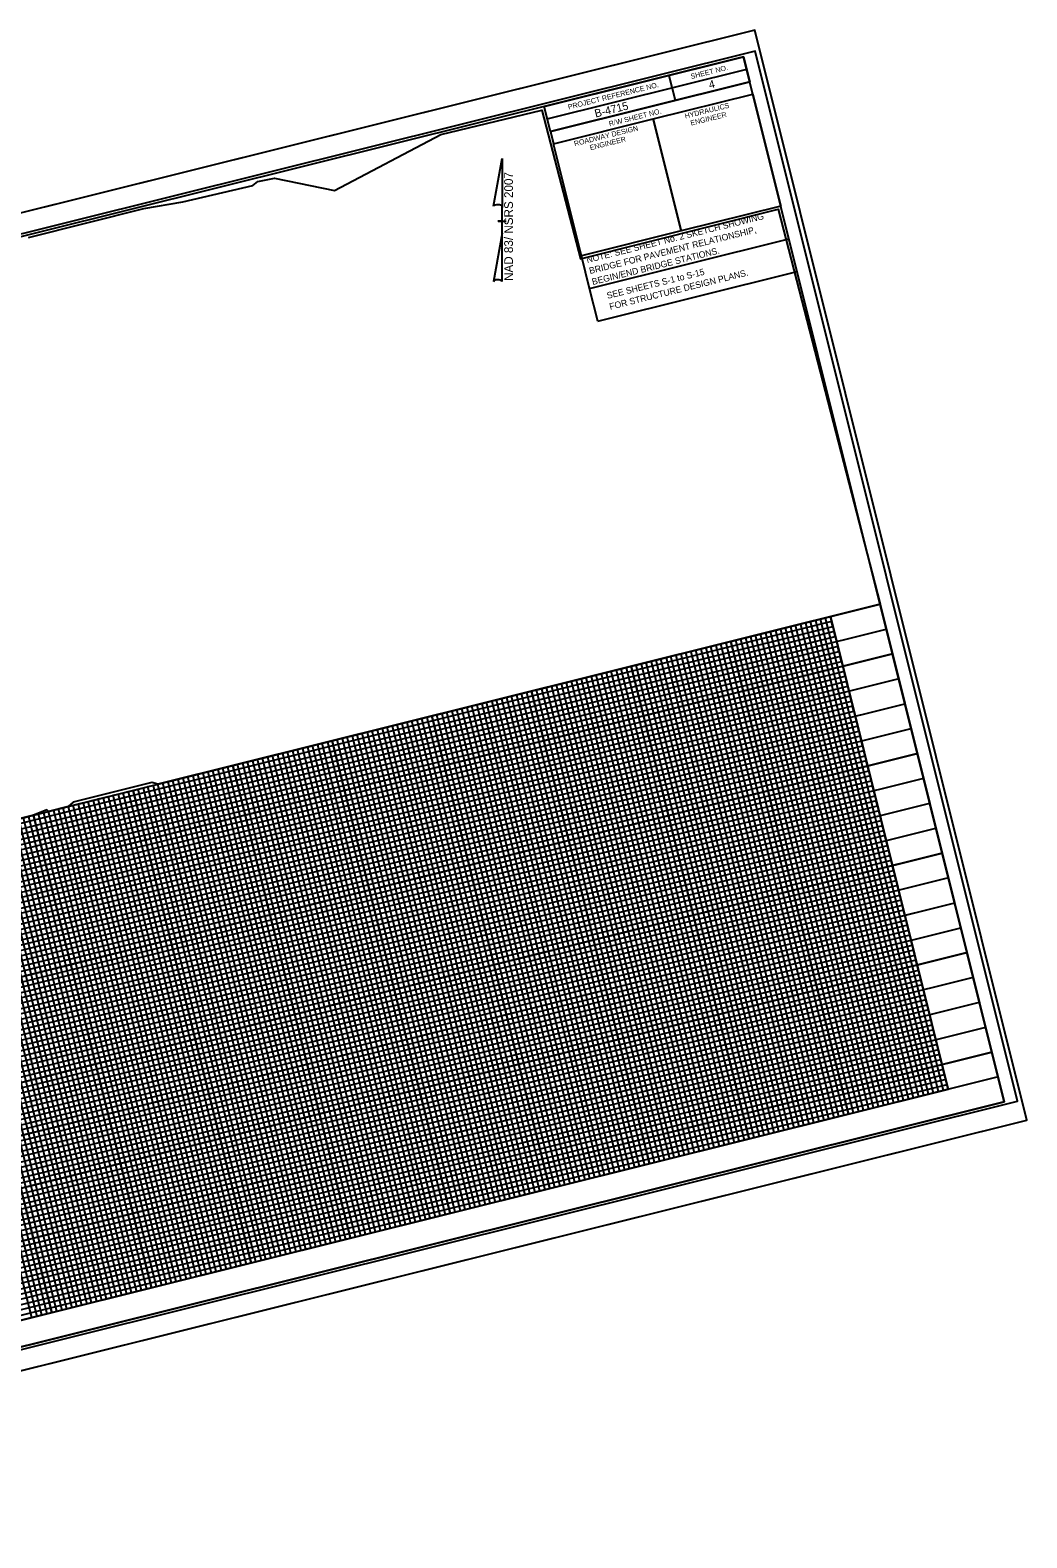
# Model space of a CAD drawing. Extents: x 1030486 to 1032384, y 655714 to 657184.
# Drawn here: x 1031413 to 1032384, y 655714 to 657184 of the extents above; entities that cross this region are included whole.
import ezdxf

# ---------------------------------------------------------------- set-up
doc = ezdxf.new("R2010")
doc.units = 0
for name, color, linetype in [('Prop Horizontal Alignment Station Label', 7, 'Continuous'), ('Prop North Arrow NAD83 for Plan Sheets CELL', 7, 'Continuous'), ('Prop Paved Shoulder', 7, 'Continuous'), ('Sheet Clip Boundary CELL', 7, 'Continuous'), ('Sheet Cutting Line CELL', 7, 'Continuous'), ('Sheet Data Field CELL', 7, 'Continuous'), ('Sheet DOT Grid CELL', 7, 'Continuous'), ('Sheet Layout Plan Border', 7, 'Continuous'), ('Sheet Layout Profile Border Port 2', 7, 'Continuous'), ('Sheet Plan And Profile CELL', 7, 'Continuous'), ('Sheet Plot Border Inside CELL', 7, 'Continuous'), ('Sheet Plot Border Outside CELL', 7, 'Continuous'), ('Sheet Profile Grid Major CELL', 7, 'Continuous'), ('Sheet Profile Grid Middle CELL', 7, 'Continuous'), ('Sheet Profile Grid Minor CELL', 7, 'Continuous')]:
    doc.layers.add(name, color=color, linetype=linetype)

msp = doc.modelspace()

# ---------------------------------------------------------------- linework, layer by layer
at = {"layer": 'Prop North Arrow NAD83 for Plan Sheets CELL'}
for p, q in [((1031864.6, 657012.3), (1031872.8, 657058.7)), ((1031872.9, 657058.7), (1031872.8, 657058.7)), ((1031872.9, 657058.7), (1031872.8, 657058.7)), ((1031872.9, 657058.7), (1031872.9, 657010.9)), ((1031872.9, 656986.1), (1031872.9, 657012.3)), ((1031872.9, 657010.9), (1031872.9, 657012.2)), ((1031868.9, 656997.7), (1031868.8, 656997.7)), ((1031868.9, 656997.7), (1031876.9, 656997.7)), ((1031872.4, 656997.7), (1031868.9, 656997.7)), ((1031872.9, 656986.1), (1031864.5, 656938.8)), ((1031872.9, 656939), (1031872.9, 656986.1))]:
    msp.add_line(p, q, dxfattribs=at)
for centre, start_param, end_param in [((1031868.7, 657011.8), 0.216388, 2.908219), ((1031868.7, 656938.6), 0.201328, 3.141593)]:
    msp.add_ellipse(centre, major_axis=(4.23, -0.03), ratio=0.461098, start_param=start_param, end_param=end_param, dxfattribs=at)
at = {"layer": 'Prop Paved Shoulder'}
msp.add_arc((1031481.8, 656722.1), 40, 14, 14, dxfattribs=at)
at = {"layer": 'Sheet Clip Boundary CELL'}
msp.add_lwpolyline([(1031411.6, 656981.9), (1031524, 657010.1), (1031562, 657016.5), (1031630.1, 657032.5), (1031634.9, 657036.5), (1031651.2, 657039.7), (1031709.5, 657027.5), (1031813, 657082.1), (1031911.7, 657106), (1031949.3, 656960.9), (1032141.6, 657009.3), (1032241.1, 656624.3), (1031853, 656527.5), (1031537.6, 656448.9), (1031531.8, 656450.5), (1031455, 656431.2), (1031450.3, 656427.1), (1031430.9, 656422.3), (1031429.3, 656423.7), (1031416.3, 656418.7), (1031314.4, 656393.3)], dxfattribs=at)
at = {"layer": 'Sheet Cutting Line CELL'}
for p, q in [((1032119.1, 657183.9), (1030485.6, 656776.6)), ((1030750.5, 655714.1), (1032384, 656121.4))]:
    msp.add_line(p, q, dxfattribs=at)
at = {"layer": 'Sheet DOT Grid CELL'}
for p, q in [((1030785.6, 656261.4), (1032241.1, 656624.3)), ((1032192.6, 656612.2), (1032307.5, 656151.3)), ((1032144, 656600.1), (1032259, 656139.2)), ((1032095.5, 656588), (1032210.4, 656127.1)), ((1030797.7, 656212.9), (1032253.2, 656575.8)), ((1032047, 656575.9), (1032161.9, 656115)), ((1031998.5, 656563.8), (1032113.4, 656102.9)), ((1031901.5, 656539.6), (1032016.4, 656078.7)), ((1031950, 656551.7), (1032064.9, 656090.8)), ((1030809.8, 656164.4), (1032265.3, 656527.3)), ((1031853, 656527.5), (1031967.9, 656066.6)), ((1031804.4, 656515.4), (1031919.4, 656054.5)), ((1031755.9, 656503.3), (1031870.8, 656042.4)), ((1030821.9, 656115.9), (1032277.4, 656478.7)), ((1031658.9, 656479.1), (1031773.8, 656018.2)), ((1031707.4, 656491.2), (1031822.3, 656030.3)), ((1031610.4, 656467), (1031725.3, 656006.1)), ((1031561.9, 656454.9), (1031676.8, 655994.1)), ((1031513.4, 656442.8), (1031628.3, 655982)), ((1030834, 656067.3), (1032289.5, 656430.2)), ((1031464.8, 656430.8), (1031579.8, 655969.9)), ((1031367.8, 656406.6), (1031482.7, 655945.7)), ((1031416.3, 656418.7), (1031531.2, 655957.8)), ((1031319.3, 656394.5), (1031434.2, 655933.6)), ((1030846.1, 656018.8), (1032301.6, 656381.7)), ((1030858.2, 655970.3), (1032313.7, 656333.2)), ((1030870.3, 655921.8), (1032325.7, 656284.7)), ((1030882.4, 655873.3), (1032337.8, 656236.2)), ((1030894.5, 655824.8), (1032349.9, 656187.7))]:
    msp.add_line(p, q, dxfattribs=at)
at = {"layer": 'Sheet Layout Plan Border'}
msp.add_lwpolyline([(1030906.6, 655776.3), (1030785.6, 656261.4), (1031949.9, 656551.7), (1032241.1, 656624.3), (1032362, 656139.1)], close=True, dxfattribs=at)
at = {"layer": 'Sheet Layout Profile Border Port 2'}
msp.add_lwpolyline([(1030834.1, 656273.5), (1032192.6, 656612.2), (1032307.5, 656151.3), (1030949.1, 655812.6)], close=True, dxfattribs=at)
at = {"layer": 'Sheet Plan And Profile CELL'}
for p, q in [((1031916.9, 657097.4), (1032111.1, 657145.8)), ((1032035.3, 657139.8), (1032041.3, 657115.5)), ((1031920, 657085.2), (1032114.1, 657133.6)), ((1032020.1, 657097.3), (1032047.3, 656988.2)), ((1031920, 657085.2), (1031923, 657073.1)), ((1031958.1, 656932.1), (1032152.3, 656980.5)), ((1031958.1, 656932.1), (1031950.2, 656964)), ((1031966.1, 656900.3), (1032160.2, 656948.7)), ((1031966.1, 656900.3), (1031958.1, 656932.1)), ((1032356, 656163.4), (1030900.5, 655800.5))]:
    msp.add_line(p, q, dxfattribs=at)
for points in [[(1032108, 657158), (1030652.6, 656795.1), (1030906.6, 655776.3), (1032362, 656139.1)], [(1031913.9, 657109.6), (1032108, 657158), (1032114.1, 657133.6), (1031920, 657085.2)], [(1032020.1, 657097.3), (1032117.1, 657121.5), (1032144.3, 657012.4), (1032047.3, 656988.2)], [(1031923, 657073.1), (1032020.1, 657097.3), (1032047.3, 656988.2), (1031950.2, 656964)]]:
    msp.add_lwpolyline(points, close=True, dxfattribs=at)
at = {"layer": 'Sheet Plot Border Inside CELL'}
msp.add_lwpolyline([(1030758.3, 655736.7), (1032374.8, 656139.7), (1032119.5, 657163.4), (1030503, 656760.4)], close=True, dxfattribs=at)
at = {"layer": 'Sheet Plot Border Outside CELL'}
msp.add_lwpolyline([(1030750.5, 655714.1), (1032384, 656121.4), (1032119.1, 657183.9), (1030485.6, 656776.6)], close=True, dxfattribs=at)
at = {"layer": 'Sheet Profile Grid Major CELL'}
for points in [[(1030785.6, 656261.4), (1032241.1, 656624.3)], [(1032307.5, 656151.3), (1032192.6, 656612.2)], [(1032210.4, 656127.1), (1032095.5, 656588), (1032144, 656600.1), (1032259, 656139.2)], [(1032253.2, 656575.8), (1030797.7, 656212.9), (1030809.8, 656164.4), (1032265.3, 656527.3)], [(1032113.4, 656102.9), (1031998.5, 656563.8), (1032047, 656575.9), (1032161.9, 656115)], [(1032016.4, 656078.7), (1031901.5, 656539.6), (1031950, 656551.7), (1032064.9, 656090.8)], [(1031919.4, 656054.5), (1031804.4, 656515.4), (1031853, 656527.5), (1031967.9, 656066.6)], [(1031822.3, 656030.3), (1031707.4, 656491.2), (1031755.9, 656503.3), (1031870.8, 656042.4)], [(1032277.4, 656478.7), (1030821.9, 656115.9), (1030834, 656067.3), (1032289.5, 656430.2)], [(1031725.3, 656006.1), (1031610.4, 656467), (1031658.9, 656479.1), (1031773.8, 656018.2)], [(1031628.3, 655982), (1031513.4, 656442.8), (1031561.9, 656454.9), (1031676.8, 655994.1)], [(1031531.2, 655957.8), (1031416.3, 656418.7), (1031464.8, 656430.8), (1031579.8, 655969.9)], [(1031434.2, 655933.6), (1031319.3, 656394.5), (1031367.8, 656406.6), (1031482.7, 655945.7)], [(1032301.6, 656381.7), (1030846.1, 656018.8), (1030858.2, 655970.3), (1032313.7, 656333.2)], [(1032325.7, 656284.7), (1030870.3, 655921.8), (1030882.4, 655873.3), (1032337.8, 656236.2)], [(1032349.9, 656187.7), (1030894.5, 655824.8)]]:
    msp.add_lwpolyline(points, dxfattribs=at)
at = {"layer": 'Sheet Profile Grid Middle CELL'}
for p, q in [((1030791.7, 656237.1), (1032247.1, 656600)), ((1032259.2, 656551.5), (1030803.8, 656188.6)), ((1030815.9, 656140.1), (1032271.3, 656503)), ((1032283.4, 656454.5), (1030828, 656091.6)), ((1030840.1, 656043.1), (1032295.5, 656406)), ((1032307.6, 656357.5), (1030852.2, 655994.6)), ((1030864.3, 655946.1), (1032319.7, 656308.9)), ((1032331.8, 656260.4), (1030876.4, 655897.5)), ((1030888.4, 655849), (1032343.9, 656211.9))]:
    msp.add_line(p, q, dxfattribs=at)
for points in [[(1032234.7, 656133.2), (1032119.8, 656594), (1032168.3, 656606.1), (1032283.2, 656145.3)], [(1032137.7, 656109), (1032022.8, 656569.9), (1032071.3, 656582), (1032186.2, 656121.1)], [(1032040.6, 656084.8), (1031925.7, 656545.7), (1031974.2, 656557.8), (1032089.2, 656096.9)], [(1031943.6, 656060.6), (1031828.7, 656521.5), (1031877.2, 656533.6), (1031992.1, 656072.7)], [(1031846.6, 656036.4), (1031731.7, 656497.3), (1031780.2, 656509.4), (1031895.1, 656048.5)], [(1031749.6, 656012.2), (1031634.6, 656473.1), (1031683.2, 656485.2), (1031798.1, 656024.3)], [(1031652.5, 655988), (1031537.6, 656448.9), (1031586.1, 656461), (1031701, 656000.1)], [(1031555.5, 655963.8), (1031440.6, 656424.7), (1031489.1, 656436.8), (1031604, 655975.9)], [(1031458.5, 655939.6), (1031343.6, 656400.5), (1031392.1, 656412.6), (1031507, 655951.7)]]:
    msp.add_lwpolyline(points, dxfattribs=at)
at = {"layer": 'Sheet Profile Grid Minor CELL'}
for points in [[(1032297.8, 656148.9), (1032182.9, 656609.8), (1032187.7, 656611), (1032302.6, 656150.1)], [(1030836.6, 656263.8), (1032195, 656602.5), (1032193.8, 656607.3), (1030835.4, 656268.7)], [(1030839, 656254.1), (1032197.4, 656592.8), (1032196.2, 656597.6), (1030837.8, 656258.9)], [(1032239.6, 656134.4), (1032124.6, 656595.3), (1032129.5, 656596.5), (1032244.4, 656135.6)], [(1032249.3, 656136.8), (1032134.3, 656597.7), (1032139.2, 656598.9), (1032254.1, 656138)], [(1032263.8, 656140.4), (1032148.9, 656601.3), (1032153.7, 656602.5), (1032268.7, 656141.6)], [(1032273.5, 656142.8), (1032158.6, 656603.7), (1032163.5, 656604.9), (1032278.4, 656144)], [(1032288.1, 656146.5), (1032173.2, 656607.4), (1032178, 656608.6), (1032292.9, 656147.7)], [(1030842.6, 656239.5), (1032201, 656578.2), (1032199.8, 656583.1), (1030841.4, 656244.4)], [(1032191, 656122.3), (1032076.1, 656583.2), (1032081, 656584.4), (1032195.9, 656123.5)], [(1032200.7, 656124.7), (1032085.8, 656585.6), (1032090.7, 656586.8), (1032205.6, 656125.9)], [(1032215.3, 656128.3), (1032100.4, 656589.2), (1032105.2, 656590.4), (1032220.1, 656129.5)], [(1032225, 656130.7), (1032110.1, 656591.6), (1032114.9, 656592.8), (1032229.8, 656131.9)], [(1030845, 656229.8), (1032203.4, 656568.5), (1032202.2, 656573.4), (1030843.8, 656234.7)], [(1032128, 656106.5), (1032013.1, 656567.4), (1032017.9, 656568.6), (1032132.8, 656107.8)], [(1032142.5, 656110.2), (1032027.6, 656571.1), (1032032.5, 656572.3), (1032147.4, 656111.4)], [(1032152.2, 656112.6), (1032037.3, 656573.5), (1032042.2, 656574.7), (1032157.1, 656113.8)], [(1032166.8, 656116.2), (1032051.9, 656577.1), (1032056.7, 656578.3), (1032171.6, 656117.4)], [(1032176.5, 656118.6), (1032061.6, 656579.5), (1032066.4, 656580.7), (1032181.3, 656119.9)], [(1030848.7, 656215.3), (1032207.1, 656554), (1032205.9, 656558.8), (1030847.5, 656220.1)], [(1032069.7, 656092), (1031954.8, 656552.9), (1031959.7, 656554.1), (1032074.6, 656093.2)], [(1032079.5, 656094.5), (1031964.5, 656555.3), (1031969.4, 656556.6), (1032084.3, 656095.7)], [(1032094, 656098.1), (1031979.1, 656559), (1031983.9, 656560.2), (1032098.9, 656099.3)], [(1032103.7, 656100.5), (1031988.8, 656561.4), (1031993.6, 656562.6), (1032108.6, 656101.7)], [(1032118.3, 656104.1), (1032003.4, 656565), (1032008.2, 656566.2), (1032123.1, 656105.3)], [(1030851.1, 656205.6), (1032209.5, 656544.3), (1032208.3, 656549.1), (1030849.9, 656210.4)], [(1032006.7, 656076.3), (1031891.8, 656537.2), (1031896.6, 656538.4), (1032011.5, 656077.5)], [(1032021.2, 656079.9), (1031906.3, 656540.8), (1031911.2, 656542), (1032026.1, 656081.1)], [(1032030.9, 656082.4), (1031916, 656543.2), (1031920.9, 656544.5), (1032035.8, 656083.6)], [(1032045.5, 656086), (1031930.6, 656546.9), (1031935.4, 656548.1), (1032050.3, 656087.2)], [(1032055.2, 656088.4), (1031940.3, 656549.3), (1031945.1, 656550.5), (1032060, 656089.6)], [(1030854.7, 656191), (1032213.1, 656529.7), (1032211.9, 656534.6), (1030853.5, 656195.9)], [(1030857.1, 656181.3), (1032215.5, 656520), (1032214.3, 656524.9), (1030855.9, 656186.2)], [(1031948.5, 656061.8), (1031833.5, 656522.7), (1031838.4, 656523.9), (1031953.3, 656063)], [(1031958.2, 656064.2), (1031843.3, 656525.1), (1031848.1, 656526.3), (1031963, 656065.4)], [(1031972.7, 656067.8), (1031857.8, 656528.7), (1031862.7, 656529.9), (1031977.6, 656069)], [(1031982.4, 656070.3), (1031867.5, 656531.1), (1031872.4, 656532.4), (1031987.3, 656071.5)], [(1031997, 656073.9), (1031882.1, 656534.8), (1031886.9, 656536), (1032001.8, 656075.1)], [(1030859.5, 656171.6), (1032218, 656510.3)], [(1031885.4, 656046.1), (1031770.5, 656507), (1031775.3, 656508.2), (1031890.2, 656047.3)], [(1031899.9, 656049.7), (1031785, 656510.6), (1031789.9, 656511.8), (1031904.8, 656050.9)], [(1031909.7, 656052.1), (1031794.7, 656513), (1031799.6, 656514.2), (1031914.5, 656053.3)], [(1031924.2, 656055.7), (1031809.3, 656516.6), (1031814.1, 656517.8), (1031929.1, 656057)], [(1031933.9, 656058.2), (1031819, 656519.1), (1031823.8, 656520.3), (1031938.8, 656059.4)], [(1030862, 656161.9), (1032220.4, 656500.6), (1032219.2, 656505.5), (1030860.8, 656166.8)], [(1030865.6, 656147.4), (1032224, 656486.1), (1032221.6, 656495.8), (1030863.2, 656157.1)], [(1031827.2, 656031.6), (1031712.3, 656492.4), (1031717.1, 656493.7), (1031832, 656032.8)], [(1031836.9, 656034), (1031722, 656494.9), (1031726.8, 656496.1), (1031841.7, 656035.2)], [(1031851.4, 656037.6), (1031736.5, 656498.5), (1031741.4, 656499.7), (1031856.3, 656038.8)], [(1031861.1, 656040), (1031746.2, 656500.9), (1031751.1, 656502.1), (1031866, 656041.2)], [(1031875.7, 656043.6), (1031760.8, 656504.5), (1031765.6, 656505.7), (1031880.5, 656044.9)], [(1030868, 656137.7), (1032226.4, 656476.4), (1032225.2, 656481.2), (1030866.8, 656142.5)], [(1031778.7, 656019.5), (1031663.7, 656480.3), (1031668.6, 656481.6), (1031783.5, 656020.7)], [(1031788.4, 656021.9), (1031673.5, 656482.8), (1031678.3, 656484), (1031793.2, 656023.1)], [(1031802.9, 656025.5), (1031688, 656486.4), (1031692.9, 656487.6), (1031807.8, 656026.7)], [(1031812.6, 656027.9), (1031697.7, 656488.8), (1031702.6, 656490), (1031817.5, 656029.1)], [(1030871.6, 656123.1), (1032230.1, 656461.8), (1032227.6, 656471.5), (1030869.2, 656132.8)], [(1031715.6, 656003.7), (1031600.7, 656464.6), (1031605.5, 656465.8), (1031720.4, 656004.9)], [(1031730.1, 656007.4), (1031615.2, 656468.2), (1031620.1, 656469.5), (1031735, 656008.6)], [(1031739.8, 656009.8), (1031624.9, 656470.7), (1031629.8, 656471.9), (1031744.7, 656011)], [(1031754.4, 656013.4), (1031639.5, 656474.3), (1031644.3, 656475.5), (1031759.3, 656014.6)], [(1031764.1, 656015.8), (1031649.2, 656476.7), (1031654, 656477.9), (1031769, 656017)], [(1030874.1, 656113.4), (1032232.5, 656452.1), (1032231.3, 656456.9), (1030872.9, 656118.3)], [(1031657.4, 655989.2), (1031542.5, 656450.1), (1031547.3, 656451.3), (1031662.2, 655990.4)], [(1031667.1, 655991.6), (1031552.2, 656452.5), (1031557, 656453.7), (1031671.9, 655992.8)], [(1031681.6, 655995.3), (1031566.7, 656456.2), (1031571.6, 656457.4), (1031686.5, 655996.5)], [(1031691.3, 655997.7), (1031576.4, 656458.6), (1031581.3, 656459.8), (1031696.2, 655998.9)], [(1031705.9, 656001.3), (1031591, 656462.2), (1031595.8, 656463.4), (1031710.7, 656002.5)], [(1030877.7, 656098.8), (1032236.1, 656437.5), (1032233.7, 656447.2), (1030875.3, 656108.6)], [(1031594.3, 655973.5), (1031479.4, 656434.4), (1031484.2, 656435.6), (1031599.2, 655974.7)], [(1031608.9, 655977.1), (1031493.9, 656438), (1031498.8, 656439.2), (1031613.7, 655978.3)], [(1031618.6, 655979.5), (1031503.6, 656440.4), (1031508.5, 656441.6), (1031623.4, 655980.7)], [(1031633.1, 655983.2), (1031518.2, 656444.1), (1031523.1, 656445.3), (1031638, 655984.4)], [(1031642.8, 655985.6), (1031527.9, 656446.5), (1031532.8, 656447.7), (1031647.7, 655986.8)], [(1030880.1, 656089.1), (1032238.5, 656427.8), (1032237.3, 656432.7), (1030878.9, 656094)], [(1030883.7, 656074.6), (1032242.2, 656413.3), (1032239.7, 656423), (1030881.3, 656084.3)], [(1031536.1, 655959), (1031421.2, 656419.9), (1031426, 656421.1), (1031540.9, 655960.2)], [(1031545.8, 655961.4), (1031430.9, 656422.3), (1031435.7, 656423.5), (1031550.6, 655962.6)], [(1031560.3, 655965), (1031445.4, 656425.9), (1031450.3, 656427.1), (1031565.2, 655966.2)], [(1031570, 655967.4), (1031455.1, 656428.3), (1031460, 656429.5), (1031574.9, 655968.7)], [(1031584.6, 655971.1), (1031469.7, 656432), (1031474.5, 656433.2), (1031589.5, 655972.3)], [(1030886.2, 656064.9), (1032244.6, 656403.6), (1032243.4, 656408.4), (1030884.9, 656069.7)], [(1031473, 655943.3), (1031358.1, 656404.1), (1031363, 656405.4), (1031477.9, 655944.5)], [(1031487.6, 655946.9), (1031372.7, 656407.8), (1031377.5, 656409), (1031492.4, 655948.1)], [(1031497.3, 655949.3), (1031382.4, 656410.2), (1031387.2, 656411.4), (1031502.1, 655950.5)], [(1031511.8, 655952.9), (1031396.9, 656413.8), (1031401.8, 656415), (1031516.7, 655954.1)], [(1031521.5, 655955.3), (1031406.6, 656416.2), (1031411.5, 656417.4), (1031526.4, 655956.6)], [(1030889.8, 656050.3), (1032248.2, 656389), (1032245.8, 656398.7), (1030887.4, 656060)], [(1031414.8, 655928.7), (1031299.9, 656389.6), (1031304.7, 656390.8), (1031419.7, 655929.9)], [(1031424.5, 655931.2), (1031309.6, 656392), (1031314.4, 656393.3), (1031429.4, 655932.4)], [(1031439.1, 655934.8), (1031324.1, 656395.7), (1031329, 656396.9), (1031443.9, 655936)], [(1031448.8, 655937.2), (1031333.8, 656398.1), (1031338.7, 656399.3), (1031453.6, 655938.4)], [(1031463.3, 655940.8), (1031348.4, 656401.7), (1031353.3, 656402.9), (1031468.2, 655942)], [(1030892.2, 656040.6), (1032250.6, 656379.3), (1032249.4, 656384.2), (1030891, 656045.5)], [(1030895.8, 656026.1), (1032254.2, 656364.8), (1032251.8, 656374.5), (1030893.4, 656035.8)], [(1030898.3, 656016.4), (1032256.7, 656355.1), (1032255.5, 656359.9), (1030897, 656021.2)], [(1030901.9, 656001.8), (1032260.3, 656340.5), (1032257.9, 656350.2), (1030899.5, 656011.5)], [(1030904.3, 655992.1), (1032262.7, 656330.8), (1032261.5, 656335.7), (1030903.1, 655997)], [(1030907.9, 655977.6), (1032266.3, 656316.3), (1032263.9, 656326), (1030905.5, 655987.3)], [(1030910.4, 655967.9), (1032268.8, 656306.6), (1032267.6, 656311.4), (1030909.1, 655972.7)], [(1030914, 655953.3), (1032272.4, 656292), (1032270, 656301.7), (1030911.6, 655963)], [(1030916.4, 655943.6), (1032274.8, 656282.3), (1032273.6, 656287.1), (1030915.2, 655948.5)], [(1030920, 655929), (1032278.4, 656267.7), (1032276, 656277.4), (1030917.6, 655938.8)], [(1030922.4, 655919.3), (1032280.9, 656258), (1032279.7, 656262.9), (1030921.2, 655924.2)], [(1030926.1, 655904.8), (1032284.5, 656243.5), (1032282.1, 656253.2), (1030923.7, 655914.5)], [(1030928.5, 655895.1), (1032286.9, 656233.8), (1032285.7, 656238.6), (1030927.3, 655899.9)], [(1030932.1, 655880.5), (1032290.5, 656219.2), (1032288.1, 656228.9), (1030929.7, 655890.2)], [(1030947.8, 655817.5), (1032306.3, 656156.2), (1032305.1, 656161), (1030946.6, 655822.3), (1030945.4, 655827.2), (1032303.8, 656165.9), (1032302.6, 656170.7), (1030944.2, 655832), (1030943, 655836.9), (1030941.8, 655841.7), (1032300.2, 656180.4), (1032299, 656185.3), (1030940.6, 655846.6), (1030939.4, 655851.4), (1032297.8, 656190.1), (1032296.6, 656195), (1030938.2, 655856.3), (1030937, 655861.1), (1030935.8, 655866), (1032294.2, 656204.7), (1032293, 656209.5), (1030934.5, 655870.8), (1030933.3, 655875.7), (1032291.7, 656214.4)]]:
    msp.add_lwpolyline(points, dxfattribs=at)

# ---------------------------------------------------------------- texts
at = {"layer": 'Prop Horizontal Alignment Station Label'}
for s, p in [('NOTE: SEE SHEET No. 2 SKETCH SHOWING', (1031955.8, 656956.8)), ('BRIDGE FOR PAVEMENT RELATIONSHIP,', (1031958.5, 656946.1)), ('BEGIN/END BRIDGE STATIONS.', (1031961.2, 656935.4)), ('SEE SHEETS S-1 to S-15', (1031975.6, 656921.9)), ('FOR STRUCTURE DESIGN PLANS.', (1031978.2, 656911.2))]:
    msp.add_text(s, height=6.3, rotation=14, dxfattribs=at).set_placement(p)
at = {"layer": 'Prop North Arrow NAD83 for Plan Sheets CELL'}
msp.add_text('NAD 83/ NSRS 2007', height=8.5, rotation=90, dxfattribs=at).set_placement((1031883.4, 656939.4))
at = {"layer": 'Sheet Data Field CELL'}
for s, p in [('4', (1032075.2, 657126.7)), ('B-4715', (1031964, 657098.7))]:
    msp.add_text(s, height=7.75, rotation=14, dxfattribs=at).set_placement(p)
at = {"layer": 'Sheet Plan And Profile CELL'}
for s, p in [('SHEET NO.', (1032057.1, 657136.2)), ('PROJECT REFERENCE NO.', (1031937.6, 657106.5)), ('HYDRAULICS', (1032051.4, 657097.6)), ('R/W SHEET NO.', (1031977.5, 657090.1)), ('ENGINEER', (1032057, 657090.8)), ('ROADWAY DESIGN', (1031943.6, 657070.7)), ('ENGINEER', (1031958.9, 657066.8))]:
    msp.add_text(s, height=5, rotation=14, dxfattribs=at).set_placement(p)

doc.saveas('drawing.dxf')
